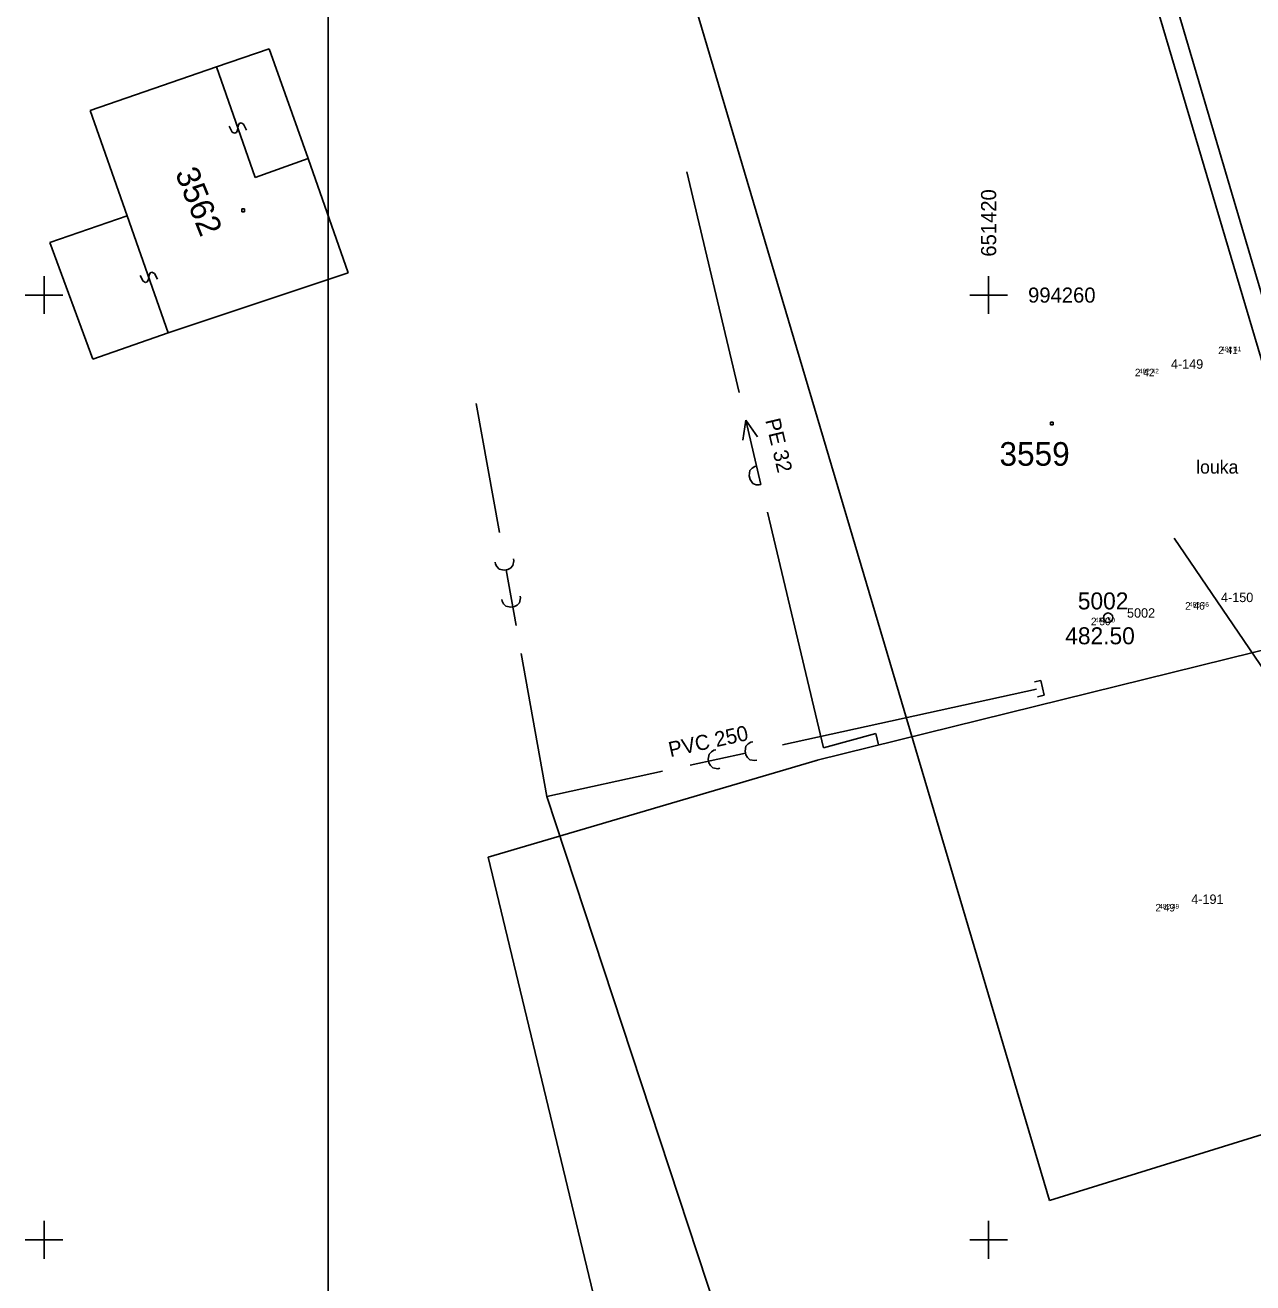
# Model space of a CAD drawing. Extents: x -651478 to -651308, y -994378 to -994071.
# Drawn here: x -651440.4 to -651414.41, y -994280.91 to -994254.29 of the extents above; entities that cross this region are included whole.
import ezdxf

# ---------------------------------------------------------------- set-up
doc = ezdxf.new("R2010")
doc.units = 0
for name, color, linetype in [('10_RAZITKO_RAMY_SEVERKA', 7, 'Continuous'), ('13_POPIS_POLOHOPISU', 7, 'Continuous'), ('18_TECKY_BODU', 7, 'Continuous'), ('19_CISLA_BODU', 7, 'Continuous'), ('20_REDUKOVANE_VYSKY_BODU', 7, 'Continuous'), ('29_PROPUSTKY', 7, 'Continuous'), ('34_KANAL-VEDENI', 7, 'Continuous'), ('38_VODA-VEDENI', 7, 'Continuous'), ('61_UPLNE_VYSKY_BODU', 7, 'Continuous'), ('_KM', 7, 'Continuous'), ('rezy', 7, 'Continuous'), ('ROZP', 7, 'Continuous')]:
    doc.layers.add(name, color=color, linetype=linetype)

# ---------------------------------------------------------------- blocks, each defined once
blk = doc.blocks.new('POINT_DISPLAY')
blk.add_line((0, 0), (0, 0))
blk = doc.blocks.new('Z105')
for radius in [0.1, 0.002]:
    blk.add_circle((0, 0), radius)
blk = doc.blocks.new('Z402')
for p, q in [((-0.02, 0.02), (0.04, 0.02)), ((-0.02, -0.04), (-0.02, 0.02)), ((0.04, 0.02), (0.04, -0.04)), ((0.04, -0.04), (-0.02, -0.04))]:
    blk.add_line(p, q)
blk = doc.blocks.new('Z218')
for p, q in [((-0.04, 0.14), (-0.08, 0.1)), ((-0.08, 0.1), (-0.08, 0.06)), ((-0.08, 0.06), (-0.04, 0.02)), ((0.1, 0.16), (-0.04, 0.14)), ((-0.04, 0.02), (0.04, -0.02)), ((0.04, -0.14), (-0.1, -0.16)), ((0.04, -0.02), (0.08, -0.06)), ((0.08, -0.1), (0.04, -0.14)), ((0.08, -0.06), (0.08, -0.1))]:
    blk.add_line(p, q)
blk = doc.blocks.new('Z70')
for p, q in [((0, -0.4), (0, 0.4)), ((-0.4, 0), (0.4, 0))]:
    blk.add_line(p, q)
blk = doc.blocks.new('Z616')
for p, q in [((-0.68, 0.1), (-0.7, 0.04)), ((-0.7, 0.04), (-0.7, 0)), ((-0.7, 0), (0.7, 0)), ((-0.64, 0.16), (-0.68, 0.1)), ((-0.54, 0.2), (-0.64, 0.16)), ((-0.46, 0.2), (-0.54, 0.2)), ((-0.36, 0.16), (-0.46, 0.2)), ((-0.32, 0.1), (-0.36, 0.16)), ((-0.3, 0.04), (-0.32, 0.1)), ((-0.3, 0), (-0.3, 0.04)), ((0.3, 0.16), (0.7, 0)), ((0.7, 0), (0.3, -0.16))]:
    blk.add_line(p, q)
blk = doc.blocks.new('Z649')
for p, q in [((-0.16, 0), (-0.16, -0.14)), ((0.16, -0.14), (0.16, 0)), ((-0.16, -0.14), (0.16, -0.14))]:
    blk.add_line(p, q)
blk = doc.blocks.new('Z627')
for p, q in [((-0.7, 0.2), (-0.66, 0.2)), ((-0.66, 0.2), (-0.56, 0.16)), ((-0.56, 0.16), (-0.52, 0.1)), ((-0.52, 0.1), (-0.5, 0.04)), ((-0.5, 0.04), (-0.5, -0.04)), ((-0.5, 0), (0.7, 0)), ((0.1, 0.2), (0.14, 0.2)), ((0.14, 0.2), (0.24, 0.16)), ((0.24, 0.16), (0.28, 0.1)), ((0.28, 0.1), (0.3, 0.04)), ((0.3, 0.04), (0.3, -0.04)), ((-0.66, -0.2), (-0.7, -0.2)), ((-0.6, -0.18), (-0.66, -0.2)), ((-0.54, -0.14), (-0.6, -0.18)), ((-0.5, -0.04), (-0.54, -0.14)), ((0.14, -0.2), (0.1, -0.2)), ((0.2, -0.18), (0.14, -0.2)), ((0.26, -0.14), (0.2, -0.18)), ((0.3, -0.04), (0.26, -0.14))]:
    blk.add_line(p, q)

msp = doc.modelspace()

# ---------------------------------------------------------------- linework, layer by layer
at = {"layer": '29_PROPUSTKY'}
msp.add_line((-651408.618, -994276.096), (-651416.071, -994265.149), dxfattribs=at)
at = {"layer": '34_KANAL-VEDENI'}
for p, q in [((-651430.359, -994265.029), (-651430.849, -994262.293)), ((-651429.357, -994270.618), (-651429.9, -994267.588)), ((-651418.985, -994268.344), (-651424.367, -994269.524)), ((-651426.906, -994270.08), (-651429.357, -994270.618)), ((-651429.357, -994270.618), (-651425.567, -994282.102))]:
    msp.add_line(p, q, dxfattribs=at)
at = {"layer": '38_VODA-VEDENI'}
for p, q in [((-651426.39, -994257.392), (-651425.281, -994262.065)), ((-651424.681, -994264.595), (-651423.497, -994269.584)), ((-651411.658, -994266.888), (-651423.661, -994269.854)), ((-651423.497, -994269.584), (-651422.391, -994269.283)), ((-651422.391, -994269.283), (-651422.331, -994269.525)), ((-651423.62, -994269.844), (-651430.599, -994271.9)), ((-651430.599, -994271.9), (-651428.225, -994281.735))]:
    msp.add_line(p, q, dxfattribs=at)
at = {"layer": '_KM'}
for p, q in [((-651420.36, -994239.17), (-651409.08, -994277.42)), ((-651418.38, -994247.36), (-651409.77, -994276.39)), ((-651427.33, -994250.12), (-651418.71, -994279.17)), ((-651436.35, -994255.17), (-651435.23, -994254.79)), ((-651435.23, -994254.79), (-651434.41, -994257.11)), ((-651439.02, -994256.09), (-651436.35, -994255.17)), ((-651436.35, -994255.17), (-651435.53, -994257.51)), ((-651439.02, -994256.09), (-651438.24, -994258.32)), ((-651435.53, -994257.51), (-651434.41, -994257.11)), ((-651434.41, -994257.11), (-651433.56, -994259.53)), ((-651439.88, -994258.89), (-651438.24, -994258.32)), ((-651438.24, -994258.32), (-651437.37, -994260.8)), ((-651439.88, -994258.89), (-651438.97, -994261.36)), ((-651437.37, -994260.8), (-651433.56, -994259.53)), ((-651438.97, -994261.36), (-651437.37, -994260.8)), ((-651418.71, -994279.17), (-651409.77, -994276.39))]:
    msp.add_line(p, q, dxfattribs=at)
at = {"layer": 'rezy'}
msp.add_line((-651433.983, -994242.69), (-651433.983, -994326.69), dxfattribs=at)

# ---------------------------------------------------------------- block references
at = {"layer": '10_RAZITKO_RAMY_SEVERKA', "rotation": -74.28509999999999}
msp.add_blockref('Z105', (-651417.47, -994266.83), dxfattribs=at)
at = {"layer": '18_TECKY_BODU'}
for p in [(-651414.81, -994261.09), (-651416.54, -994261.56), (-651415.48, -994266.5), (-651417.47, -994266.83), (-651416.11, -994272.89)]:
    msp.add_blockref('POINT_DISPLAY', p, dxfattribs=at)
at = {"layer": '34_KANAL-VEDENI'}
for name, p, rotation in [('Z627', (-651430.13, -994266.308), -79.83870000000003), ('Z649', (-651418.996, -994268.347), 102.3625), ('Z627', (-651425.636, -994269.802), -167.63750000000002)]:
    msp.add_blockref(name, p, dxfattribs=dict(at, rotation=rotation))
at = {"layer": '38_VODA-VEDENI', "rotation": 103.3473}
msp.add_blockref('Z616', (-651424.981, -994263.33), dxfattribs=at)
at = {"layer": '_KM'}
for p, rotation in [((-651435.897, -994256.464), 109.3119), ((-651437.783, -994259.624), 109.33119999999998)]:
    msp.add_blockref('Z218', p, dxfattribs=dict(at, rotation=rotation))
for p in [(-651435.794, -994258.197), (-651418.67, -994262.709)]:
    msp.add_blockref('Z402', p, dxfattribs=at)
at = {"layer": 'ROZP'}
for p in [(-651440, -994260), (-651420, -994260), (-651440, -994280), (-651420, -994280)]:
    msp.add_blockref('Z70', p, dxfattribs=at)

# ---------------------------------------------------------------- texts
at = {"layer": '10_RAZITKO_RAMY_SEVERKA'}
for s, p in [('5002', (-651418.111, -994266.655)), ('482.50', (-651418.377, -994267.393))]:
    msp.add_text(s, height=0.36, dxfattribs=at).set_placement(p)
at = {"layer": '13_POPIS_POLOHOPISU'}
msp.add_text('louka', height=0.28, dxfattribs=at).set_placement((-651415.606, -994263.779))
at = {"layer": '19_CISLA_BODU'}
for s, p in [('4-149', (-651416.14, -994261.56)), ('4-150', (-651415.08, -994266.5)), ('5002', (-651417.07, -994266.83)), ('4-191', (-651415.71, -994272.89))]:
    msp.add_text(s, height=0.2, dxfattribs=at).set_placement(p)
at = {"layer": '20_REDUKOVANE_VYSKY_BODU'}
for s, p in [(' 2 41', (-651415.199, -994261.25)), (' 2 42', (-651416.963, -994261.72)), (' 2 46', (-651415.899, -994266.66)), (' 2 50', (-651417.893, -994266.99)), (' 2 49', (-651416.529, -994273.05))]:
    msp.add_text(s, height=0.16, dxfattribs=at).set_placement(p)
at = {"layer": '34_KANAL-VEDENI'}
msp.add_text('PVC 250', height=0.32, rotation=12.3625, dxfattribs=at).set_placement((-651426.739, -994269.784))
at = {"layer": '38_VODA-VEDENI'}
msp.add_text('PE 32', height=0.32, rotation=283.3473, dxfattribs=at).set_placement((-651424.731, -994262.649))
at = {"layer": '61_UPLNE_VYSKY_BODU'}
for s, p in [('482 41 ', (-651415.073, -994261.19)), ('482 42 ', (-651416.818, -994261.66)), ('482 46 ', (-651415.758, -994266.6)), ('482 50 ', (-651417.748, -994266.93)), ('482 49 ', (-651416.388, -994272.99))]:
    msp.add_text(s, height=0.1, dxfattribs=at).set_placement(p)
at = {"layer": '_KM'}
msp.add_text('3562', height=0.5, rotation=291.9841, dxfattribs=at).set_placement((-651437.232, -994257.415))
msp.add_text('3559', height=0.5, dxfattribs=at).set_placement((-651419.77, -994263.613))
at = {"layer": 'ROZP'}
msp.add_text('651420', height=0.32, rotation=90, dxfattribs=at).set_placement((-651419.84, -994259.187))
msp.add_text('994260', height=0.32, dxfattribs=at).set_placement((-651419.164, -994260.16))

doc.saveas('drawing.dxf')
